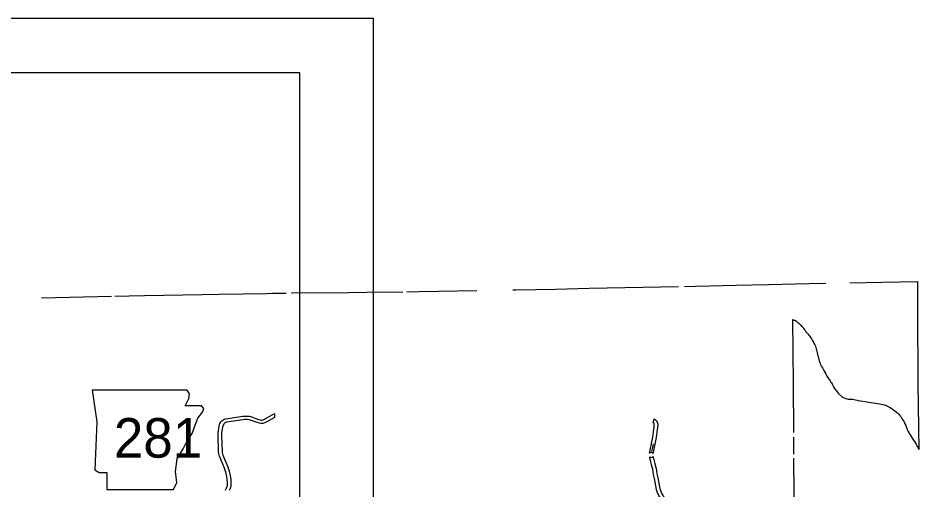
# Model space of a CAD drawing. Extents: x 77230 to 630905, y 790554 to 1662844.
# Drawn here: x 565999 to 630905, y 1628851 to 1662844 of the extents above; entities that cross this region are included whole.
import ezdxf

# ---------------------------------------------------------------- set-up
doc = ezdxf.new("R2010")
doc.units = 0
for name, color, linetype in [('Level 1', 7, 'Continuous'), ('Level 10', 7, 'Continuous'), ('Level 24', 7, 'Continuous'), ('Level 28', 7, 'Continuous'), ('Level 43', 7, 'Continuous')]:
    doc.layers.add(name, color=color, linetype=linetype)

msp = doc.modelspace()

# ---------------------------------------------------------------- linework, layer by layer
at = {"layer": 'Level 1'}
for points in [[(601638, 1643270), (601875, 1643274), (604728, 1643326), (607156, 1643378), (613588, 1643506)], [(614006, 1643514), (614801, 1643530), (617730, 1643597), (620076, 1643650), (622988, 1643719)], [(622988, 1643719), (624195, 1643737)], [(625925, 1643765), (628258, 1643823), (630810, 1643876)], [(585312, 1643009), (584289, 1642992), (583897, 1642987), (580481, 1642934), (579271, 1642918), (575102, 1642829), (574016, 1642808), (572967, 1642785)], [(588526, 1643049), (585764, 1643017), (585691, 1643016)], [(588526, 1643049), (591121, 1643087), (593715, 1643120)], [(594007, 1643124), (594893, 1643135), (599048, 1643220)], [(572723, 1642779), (568691, 1642691), (567687, 1642661)]]:
    msp.add_lwpolyline(points, dxfattribs=at)
at = {"layer": 'Level 10'}
for points in [[(581084, 1629233), (581087, 1629397), (581075, 1629586), (581044, 1629814), (580968, 1630139), (580929, 1630283), (580875, 1630432), (580521, 1631279), (580464, 1631490), (580446, 1631606), (580414, 1632778), (580417, 1632974), (580483, 1633441), (580512, 1633551), (580543, 1633635), (580615, 1633749), (580683, 1633821), (580760, 1633884), (580816, 1633920), (580865, 1633946), (580947, 1633972), (581133, 1634011), (582170, 1634161), (582293, 1634170), (582520, 1634172), (582657, 1634160), (582739, 1634143), (582815, 1634119), (583316, 1633939), (583447, 1633899), (583518, 1633885), (583550, 1633885), (583586, 1633888), (583662, 1633915), (583810, 1633983), (584470, 1634367), (584476, 1634081)], [(584476, 1634081), (583925, 1633760), (583756, 1633683), (583641, 1633643), (583560, 1633634), (583492, 1633636), (583387, 1633655), (583237, 1633702), (582735, 1633882), (582676, 1633900), (582620, 1633912), (582510, 1633922), (582303, 1633920), (582196, 1633913), (581176, 1633765), (581011, 1633730), (580962, 1633714), (580943, 1633705), (580908, 1633681), (580853, 1633637), (580814, 1633595), (580768, 1633523), (580750, 1633475), (580729, 1633392), (580667, 1632954), (580664, 1632779), (580695, 1631629), (580709, 1631542), (580758, 1631360), (581108, 1630523), (581168, 1630359), (581211, 1630200), (581290, 1629860), (581324, 1629611), (581337, 1629402), (581334, 1629229)], [(611746, 1633716), (611819, 1633976), (611895, 1633918), (611922, 1633896), (611955, 1633867), (611973, 1633848), (611993, 1633826), (612004, 1633810), (612013, 1633798), (612022, 1633783), (612032, 1633766), (612043, 1633741), (612054, 1633717), (612065, 1633687), (612070, 1633669), (612076, 1633646), (612082, 1633613), (612084, 1633579), (612084, 1633537), (612085, 1633492), (612084, 1633453), (612083, 1633438), (612082, 1633413), (612079, 1633386), (612076, 1633364), (612053, 1633209)], [(611806, 1633243), (611828, 1633400), (611831, 1633419), (611833, 1633434), (611833, 1633448), (611834, 1633460), (611835, 1633494), (611834, 1633535), (611834, 1633570), (611833, 1633584), (611832, 1633593), (611829, 1633603), (611827, 1633612), (611822, 1633624), (611816, 1633637), (611809, 1633652), (611808, 1633654), (611804, 1633660), (611801, 1633664), (611799, 1633667), (611789, 1633679), (611783, 1633685), (611761, 1633704), (611746, 1633716)], [(611640, 1632206), (611725, 1632661), (611806, 1633243)], [(612053, 1633209), (611972, 1632621), (611885, 1632155)], [(611497, 1631500), (611501, 1631534), (611512, 1631601), (611558, 1631840), (611640, 1632206)], [(611763, 1632180), (611680, 1631815), (611642, 1631612)], [(611885, 1632155), (611802, 1631789), (611758, 1631558), (611747, 1631488)], [(612461, 1627963), (612252, 1628310), (612161, 1628461), (612128, 1628523), (612090, 1628600), (612047, 1628721), (612001, 1628861), (611963, 1629018), (611939, 1629147), (611842, 1629677), (611783, 1629956), (611720, 1630342), (611665, 1630570), (611633, 1630696), (611560, 1630975), (611541, 1631046), (611530, 1631097), (611518, 1631152), (611504, 1631237)], [(611753, 1631262), (611764, 1631199), (611775, 1631148), (611784, 1631104), (611801, 1631040), (611875, 1630759), (611908, 1630630), (611965, 1630391), (612029, 1630003), (612088, 1629725), (612185, 1629192), (612208, 1629070), (612242, 1628929), (612283, 1628802), (612321, 1628697), (612350, 1628637), (612378, 1628585), (612466, 1628439), (612668, 1628104)], [(580941, 1628838), (580980, 1628900), (581004, 1628948), (581016, 1628976), (581028, 1629004), (581039, 1629031), (581049, 1629060), (581058, 1629090), (581067, 1629124), (581075, 1629156), (581080, 1629180), (581084, 1629233)], [(581334, 1629229), (581327, 1629140), (581319, 1629101), (581309, 1629060), (581297, 1629019), (581287, 1628985), (581275, 1628947), (581259, 1628909), (581245, 1628876), (581230, 1628841)]]:
    msp.add_lwpolyline(points, dxfattribs=at)
for start, end in [(41.72898, 132.90428), (229.93434, 321.39653)]:
    msp.add_arc((611616, 1631371), 175, start, end, dxfattribs=at)
at = {"layer": 'Level 24'}
msp.add_lwpolyline([(571341, 1636043), (571684, 1633759), (571531, 1630295), (571836, 1630105), (572407, 1630105), (572407, 1628887), (577203, 1628887), (577431, 1629382), (577355, 1630181), (577469, 1631095), (577888, 1631818), (578155, 1632351), (578535, 1632922), (578764, 1633531), (578954, 1634026), (579297, 1634444), (579373, 1634711), (579220, 1634901), (578040, 1634901), (578307, 1635434), (578345, 1635777), (578187, 1636040)], close=True, dxfattribs=at)
msp.add_lwpolyline([(571341, 1636043), (571684, 1633759), (571531, 1630295), (571836, 1630105), (572407, 1630105), (572407, 1628887), (577203, 1628887), (577431, 1629382), (577355, 1630181), (577469, 1631095), (577888, 1631818), (578155, 1632351), (578535, 1632922), (578764, 1633531), (578954, 1634026), (579297, 1634444), (579373, 1634711), (579220, 1634901), (578040, 1634901), (578307, 1635434), (578345, 1635777), (578187, 1636040)], close=True, dxfattribs=at)
at = {"layer": 'Level 28'}
for p, q in [((295896, 1662844), (591576, 1662844)), ((591576, 1662844), (591576, 1483324)), ((586296, 1658884), (311736, 1658884)), ((586296, 1488604), (586296, 1658884)), ((586296, 1658884), (586296, 1658884))]:
    msp.add_line(p, q, dxfattribs=at)
at = {"layer": 'Level 43'}
for points in [[(630810, 1643876), (630810, 1641780), (630824, 1636493), (630905, 1631777)], [(621789, 1641126), (621851, 1641107), (621883, 1641096), (621908, 1641088), (621930, 1641075), (621942, 1641069), (621971, 1641058), (621999, 1641046), (622041, 1641023), (622073, 1641003), (622115, 1640970), (622156, 1640944), (622209, 1640900), (622274, 1640838), (622321, 1640794), (622387, 1640728), (622453, 1640657), (622508, 1640600), (622550, 1640551), (622614, 1640464), (622658, 1640396), (622722, 1640307), (622765, 1640237), (622828, 1640164), (622890, 1640096), (622963, 1640013), (623004, 1639969), (623063, 1639883), (623110, 1639814), (623158, 1639734), (623210, 1639649), (623268, 1639561), (623334, 1639447), (623363, 1639386), (623399, 1639312), (623442, 1639205), (623474, 1639122), (623505, 1639022), (623526, 1638941), (623552, 1638845), (623578, 1638738), (623603, 1638641), (623625, 1638555), (623651, 1638447), (623670, 1638368), (623698, 1638238), (623719, 1638161), (623743, 1638084), (623777, 1637993), (623795, 1637938), (623818, 1637882), (623860, 1637788), (623888, 1637742), (623945, 1637648), (623996, 1637556), (624057, 1637447), (624126, 1637331), (624186, 1637213), (624233, 1637126), (624275, 1637051), (624335, 1636949), (624406, 1636844), (624450, 1636782), (624496, 1636711), (624541, 1636644), (624576, 1636599), (624599, 1636564), (624639, 1636504), (624678, 1636425), (624755, 1636269)], [(621789, 1641126), (621839, 1636524), (621859, 1632981)], [(624755, 1636269), (624810, 1636165), (624873, 1636094), (624935, 1636027), (625041, 1635891), (625094, 1635828), (625134, 1635780), (625242, 1635665), (625290, 1635629), (625383, 1635563), (625445, 1635521), (625556, 1635461), (625702, 1635417), (625801, 1635400), (625905, 1635395), (626009, 1635392), (626125, 1635382), (626227, 1635375), (626335, 1635352), (626451, 1635326), (626559, 1635294), (626695, 1635263), (626863, 1635239), (626996, 1635224), (627155, 1635210), (627299, 1635186), (627459, 1635156), (627763, 1635107), (627943, 1635081), (628057, 1635062), (628178, 1635042), (628294, 1635019), (628397, 1634993), (628543, 1634939), (628642, 1634890), (628732, 1634837), (628824, 1634781), (628919, 1634723), (629037, 1634651), (629177, 1634552), (629265, 1634486), (629384, 1634382), (629454, 1634307), (629527, 1634222), (629586, 1634142), (629657, 1634039), (629705, 1633962), (629776, 1633847), (629829, 1633749), (629855, 1633697), (629892, 1633614), (629953, 1633484), (629976, 1633425), (630000, 1633354), (630028, 1633277), (630055, 1633205), (630095, 1633118), (630127, 1633056), (630166, 1632988), (630207, 1632918), (630263, 1632816), (630403, 1632590), (630462, 1632504), (630507, 1632444), (630583, 1632343), (630660, 1632220), (630704, 1632148), (630726, 1632103), (630753, 1632054), (630785, 1631993), (630809, 1631950), (630840, 1631893), (630905, 1631777)], [(621861, 1632652), (621868, 1631425)], [(621870, 1631143), (621913, 1625874), (621862, 1620576)]]:
    msp.add_lwpolyline(points, dxfattribs=at)

# ---------------------------------------------------------------- texts
at = {"layer": 'Level 24'}
msp.add_text('281', height=2851.2, dxfattribs=at).set_placement((572905, 1631179))
msp.add_text('281', height=2851.2, dxfattribs=at).set_placement((572905, 1631179))

doc.saveas('drawing.dxf')
